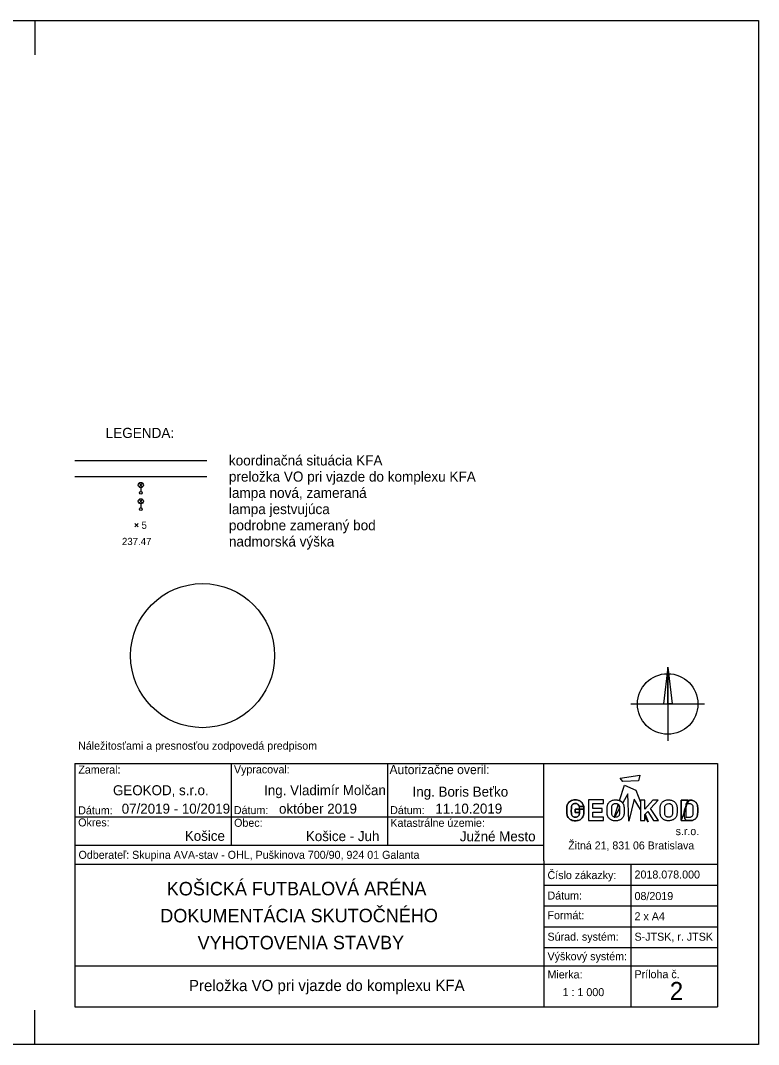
# Model space of a CAD drawing. Extents: x -263861 to -263441, y -1242367 to -1242070.
# Drawn here: x -263655.6 to -263441.4, y -1242367.2 to -1242070.2 of the extents above; entities that cross this region are included whole.
import ezdxf

# ---------------------------------------------------------------- set-up
doc = ezdxf.new("R2010")
doc.units = 0
for name, color, linetype in [('LEGENDA', 7, 'Continuous'), ('RAM_NA_TLAC_A3_1-1000', 7, 'Continuous'), ('ROZPISKA', 7, 'Continuous')]:
    doc.layers.add(name, color=color, linetype=linetype)

msp = doc.modelspace()

# ---------------------------------------------------------------- linework, layer by layer
at = {"layer": 'LEGENDA'}
for p, q in [((-263639.85, -1242197.79), (-263601.57, -1242197.79)), ((-263639.85, -1242202.49), (-263601.57, -1242202.49)), ((-263621.24, -1242205.47), (-263620.18, -1242204.41)), ((-263621.24, -1242204.41), (-263620.18, -1242205.47)), ((-263620.71, -1242205.69), (-263620.71, -1242206.79)), ((-263621.24, -1242210.18), (-263620.18, -1242209.12)), ((-263621.24, -1242209.12), (-263620.18, -1242210.18)), ((-263620.71, -1242210.4), (-263620.71, -1242211.5)), ((-263622.44, -1242217.06), (-263621.52, -1242216.14)), ((-263621.52, -1242217.06), (-263622.44, -1242216.14))]:
    msp.add_line(p, q, dxfattribs=at)
for centre, radius in [((-263620.71, -1242204.94), 0.75), ((-263620.71, -1242207.19), 0.4), ((-263620.71, -1242209.65), 0.75), ((-263620.71, -1242211.9), 0.4)]:
    msp.add_circle(centre, radius, dxfattribs=at)
at = {"layer": 'RAM_NA_TLAC_A3_1-1000'}
for p, q in [((-263651.44, -1242070.21), (-263651.44, -1242080.21)), ((-263441.44, -1242070.21), (-263441.44, -1242080.21)), ((-263651.44, -1242367.21), (-263651.44, -1242357.21))]:
    msp.add_line(p, q, dxfattribs=at)
msp.add_lwpolyline([(-263861.44, -1242070.21), (-263441.44, -1242070.21), (-263441.44, -1242367.21), (-263861.44, -1242367.21)], close=True, dxfattribs=at)
at = {"layer": 'ROZPISKA'}
for p, q in [((-263467.81, -1242257.78), (-263469.07, -1242268.44)), ((-263467.81, -1242257.78), (-263467.81, -1242279.1)), ((-263467.81, -1242257.78), (-263466.55, -1242268.44)), ((-263478.47, -1242268.44), (-263457.15, -1242268.44)), ((-263639.85, -1242285.66), (-263453.32, -1242285.66)), ((-263639.85, -1242285.66), (-263639.85, -1242356.25)), ((-263594.49, -1242285.66), (-263594.47, -1242309.37)), ((-263503.73, -1242313.89), (-263503.73, -1242285.66)), ((-263453.32, -1242285.66), (-263453.31, -1242356.25)), ((-263549.11, -1242285.67), (-263549.1, -1242309.36)), ((-263481.81, -1242296.44), (-263480.34, -1242292.01)), ((-263479.41, -1242294.53), (-263480.87, -1242297.14)), ((-263480.34, -1242292.01), (-263477.09, -1242293.39)), ((-263479.13, -1242302.43), (-263479.41, -1242294.53)), ((-263477.09, -1242293.39), (-263475.72, -1242296.88)), ((-263482.17, -1242297.54), (-263483.38, -1242301.22)), ((-263483, -1242296.23), (-263482.89, -1242296.22)), ((-263482.97, -1242297.29), (-263482.9, -1242297.29)), ((-263482.97, -1242297.29), (-263482.9, -1242297.29)), ((-263477.57, -1242296.03), (-263479.13, -1242302.43)), ((-263475.72, -1242299), (-263477.57, -1242296.03)), ((-263474.45, -1242296.3), (-263475.72, -1242296.3)), ((-263475.72, -1242296.88), (-263475.72, -1242299)), ((-263472.14, -1242296.3), (-263474.45, -1242298.91)), ((-263474.45, -1242298.91), (-263474.45, -1242296.3)), ((-263472.75, -1242298.71), (-263470.56, -1242296.3)), ((-263470.56, -1242296.3), (-263472.14, -1242296.3)), ((-263463.85, -1242296.32), (-263461.94, -1242296.32)), ((-263463.85, -1242302.28), (-263463.85, -1242296.32)), ((-263463.85, -1242296.32), (-263463.85, -1242302.28)), ((-263461.94, -1242296.32), (-263463.85, -1242296.32)), ((-263462.54, -1242297.36), (-263462.54, -1242301.24)), ((-263462.54, -1242297.36), (-263462.54, -1242301.24)), ((-263492.13, -1242298.15), (-263493.46, -1242298.15)), ((-263493.46, -1242298.15), (-263492.13, -1242298.15)), ((-263474.34, -1242300.38), (-263473.45, -1242302.66)), ((-263470.44, -1242302.28), (-263472.75, -1242298.71)), ((-263639.86, -1242301.15), (-263503.73, -1242301.15)), ((-263473.45, -1242302.66), (-263474.45, -1242301.05)), ((-263471.94, -1242302.28), (-263470.44, -1242302.28)), ((-263639.85, -1242309.36), (-263503.73, -1242309.35)), ((-263639.87, -1242314.91), (-263503.71, -1242314.9)), ((-263503.73, -1242313.89), (-263503.73, -1242332.05)), ((-263503.71, -1242314.9), (-263453.31, -1242314.9)), ((-263478.52, -1242314.91), (-263478.52, -1242333.06)), ((-263503.73, -1242320.95), (-263453.32, -1242320.96)), ((-263503.74, -1242327), (-263453.31, -1242327)), ((-263503.74, -1242333.05), (-263453.3, -1242333.06)), ((-263503.73, -1242332.05), (-263503.73, -1242356.24)), ((-263478.52, -1242333.06), (-263478.51, -1242356.24)), ((-263503.73, -1242339.11), (-263453.31, -1242339.1)), ((-263639.85, -1242344.35), (-263453.31, -1242344.34)), ((-263639.85, -1242356.25), (-263453.31, -1242356.25))]:
    msp.add_line(p, q, dxfattribs=at)
for points in [[(-263467.81, -1242257.78), (-263466.55, -1242268.44), (-263467.81, -1242268.44)], [(-263481.64, -1242289.95), (-263475.86, -1242289.12), (-263476.27, -1242290.77), (-263480.87, -1242290.92)], [(-263490.82, -1242296.28), (-263490.82, -1242302.28), (-263486.43, -1242302.28), (-263486.43, -1242301.22), (-263489.5, -1242301.22), (-263489.5, -1242299.78), (-263486.87, -1242299.78), (-263486.87, -1242298.74), (-263489.5, -1242298.74), (-263489.5, -1242297.34), (-263486.43, -1242297.34), (-263486.43, -1242296.28)]]:
    msp.add_lwpolyline(points, close=True, dxfattribs=at)
for points in [[(-263481.77, -1242298.75), (-263481.78, -1242298.62), (-263481.78, -1242298.46), (-263481.79, -1242298.31), (-263481.82, -1242298.16), (-263481.85, -1242298.03), (-263481.91, -1242297.88), (-263481.99, -1242297.74), (-263482.07, -1242297.63), (-263482.17, -1242297.54)], [(-263480.87, -1242297.14), (-263480.91, -1242297.08), (-263480.99, -1242297), (-263481.06, -1242296.92), (-263481.15, -1242296.85), (-263481.24, -1242296.78), (-263481.34, -1242296.7), (-263481.42, -1242296.65), (-263481.51, -1242296.59), (-263481.62, -1242296.53), (-263481.71, -1242296.48), (-263481.81, -1242296.44)], [(-263475.72, -1242296.3), (-263475.72, -1242302.28), (-263474.45, -1242302.28), (-263474.45, -1242300.49), (-263473.6, -1242299.6), (-263471.94, -1242302.28)], [(-263493.41, -1242299.92), (-263494.67, -1242299.92), (-263494.67, -1242298.93), (-263492.12, -1242298.93)], [(-263492.12, -1242298.93), (-263494.67, -1242298.93), (-263494.67, -1242299.92), (-263493.41, -1242299.92)], [(-263483.18, -1242301.27), (-263481.77, -1242298.75)], [(-263474.45, -1242301.05), (-263474.45, -1242300.49), (-263474.34, -1242300.38)], [(-263483.38, -1242301.22), (-263483.35, -1242301.23), (-263483.31, -1242301.24), (-263483.28, -1242301.25), (-263483.24, -1242301.26), (-263483.2, -1242301.27), (-263483.18, -1242301.27)]]:
    msp.add_lwpolyline(points, dxfattribs=at)
for centre, radius in [((-263602.79, -1242254.42), 20.9), ((-263467.81, -1242268.44), 8.78)]:
    msp.add_circle(centre, radius, dxfattribs=at)
for points in [[(-263492.12, -1242298.93), (-263492.12, -1242299.69), (-263492.13, -1242300.37), (-263492.27, -1242300.97), (-263492.56, -1242301.46), (-263493.01, -1242301.86), (-263493.48, -1242302.14), (-263494.1, -1242302.29), (-263494.66, -1242302.33), (-263495.24, -1242302.29), (-263495.83, -1242302.1), (-263496.33, -1242301.77), (-263496.72, -1242301.38), (-263496.97, -1242300.85), (-263497.09, -1242300.27), (-263497.11, -1242299.88), (-263497.11, -1242298.7), (-263497.07, -1242298.06), (-263496.89, -1242297.51), (-263496.6, -1242297.05), (-263496.02, -1242296.58), (-263495.4, -1242296.31), (-263494.68, -1242296.23), (-263493.92, -1242296.29), (-263493.13, -1242296.62), (-263492.5, -1242297.2), (-263492.13, -1242298.15), (-263492.12, -1242298.93), (-263492.13, -1242298.15)], [(-263492.13, -1242298.15), (-263492.5, -1242297.2), (-263493.13, -1242296.62), (-263493.92, -1242296.29), (-263494.68, -1242296.23), (-263495.4, -1242296.31), (-263496.02, -1242296.58), (-263496.6, -1242297.05), (-263496.89, -1242297.51), (-263497.07, -1242298.06), (-263497.11, -1242298.7), (-263497.11, -1242299.88), (-263497.09, -1242300.27), (-263496.97, -1242300.85), (-263496.72, -1242301.38), (-263496.33, -1242301.77), (-263495.83, -1242302.1), (-263495.24, -1242302.29), (-263494.66, -1242302.33), (-263494.1, -1242302.29), (-263493.48, -1242302.14), (-263493.01, -1242301.86), (-263492.56, -1242301.46), (-263492.27, -1242300.97), (-263492.13, -1242300.37), (-263492.12, -1242299.69), (-263492.12, -1242298.93), (-263492.13, -1242298.15), (-263492.12, -1242298.93)], [(-263493.45, -1242298.15), (-263493.58, -1242297.83), (-263493.87, -1242297.51), (-263494.27, -1242297.32), (-263494.66, -1242297.29), (-263495.06, -1242297.34), (-263495.38, -1242297.52), (-263495.62, -1242297.78), (-263495.73, -1242298.05), (-263495.74, -1242298.46), (-263495.77, -1242298.9), (-263495.78, -1242299.44), (-263495.77, -1242300.07), (-263495.72, -1242300.54), (-263495.55, -1242300.91), (-263495.3, -1242301.12), (-263494.99, -1242301.25), (-263494.67, -1242301.28), (-263494.29, -1242301.26), (-263493.9, -1242301.1), (-263493.61, -1242300.83), (-263493.45, -1242300.52), (-263493.41, -1242300.16), (-263493.41, -1242299.92), (-263493.45, -1242298.15), (-263493.41, -1242299.92)], [(-263493.41, -1242299.92), (-263493.41, -1242300.16), (-263493.45, -1242300.52), (-263493.61, -1242300.83), (-263493.9, -1242301.1), (-263494.29, -1242301.26), (-263494.67, -1242301.28), (-263494.99, -1242301.25), (-263495.3, -1242301.12), (-263495.55, -1242300.91), (-263495.72, -1242300.54), (-263495.77, -1242300.07), (-263495.78, -1242299.44), (-263495.77, -1242298.9), (-263495.74, -1242298.46), (-263495.73, -1242298.05), (-263495.62, -1242297.78), (-263495.38, -1242297.52), (-263495.06, -1242297.34), (-263494.66, -1242297.29), (-263494.27, -1242297.32), (-263493.87, -1242297.51), (-263493.58, -1242297.83), (-263493.45, -1242298.15), (-263493.41, -1242299.92), (-263493.45, -1242298.15)], [(-263482.89, -1242296.22), (-263482.86, -1242296.22), (-263482.68, -1242296.22), (-263482.35, -1242296.3), (-263481.89, -1242296.38), (-263481.47, -1242296.61), (-263481.08, -1242296.88), (-263480.76, -1242297.25), (-263480.58, -1242297.67), (-263480.47, -1242298.13), (-263480.47, -1242298.85), (-263480.45, -1242299.6), (-263480.46, -1242300.33), (-263480.53, -1242300.79), (-263480.7, -1242301.18), (-263480.92, -1242301.52), (-263481.23, -1242301.78), (-263481.55, -1242302.02), (-263481.95, -1242302.18), (-263482.39, -1242302.31), (-263482.87, -1242302.34), (-263483.31, -1242302.31), (-263483.71, -1242302.27), (-263484.05, -1242302.12), (-263484.38, -1242301.93), (-263484.69, -1242301.73), (-263484.97, -1242301.44), (-263485.19, -1242301.05), (-263485.35, -1242300.57), (-263485.41, -1242299.8), (-263485.35, -1242299.07), (-263485.38, -1242298.37), (-263485.32, -1242297.97), (-263485.23, -1242297.58), (-263485.04, -1242297.23), (-263484.79, -1242296.95), (-263484.52, -1242296.69), (-263484.18, -1242296.51), (-263483.79, -1242296.34), (-263483.38, -1242296.25), (-263483.11, -1242296.23), (-263483, -1242296.23)], [(-263482.9, -1242297.29), (-263482.85, -1242297.29), (-263482.71, -1242297.3), (-263482.47, -1242297.35), (-263482.21, -1242297.49), (-263481.97, -1242297.71), (-263481.82, -1242298.05), (-263481.76, -1242298.42), (-263481.77, -1242298.82), (-263481.76, -1242299.25), (-263481.78, -1242299.69), (-263481.76, -1242300.09), (-263481.82, -1242300.43), (-263481.89, -1242300.74), (-263482.09, -1242301.02), (-263482.37, -1242301.2), (-263482.68, -1242301.29), (-263482.93, -1242301.27), (-263483.15, -1242301.28), (-263483.4, -1242301.23), (-263483.63, -1242301.08), (-263483.86, -1242300.86), (-263484.02, -1242300.54), (-263484.07, -1242300.15), (-263484.05, -1242299.67), (-263484.06, -1242299.15), (-263484.05, -1242298.64), (-263484.04, -1242298.23), (-263483.97, -1242297.9), (-263483.79, -1242297.64), (-263483.54, -1242297.44), (-263483.26, -1242297.31), (-263483.06, -1242297.3), (-263482.97, -1242297.29)], [(-263482.9, -1242297.29), (-263482.85, -1242297.29), (-263482.71, -1242297.3), (-263482.47, -1242297.35), (-263482.21, -1242297.49), (-263481.97, -1242297.71), (-263481.82, -1242298.05), (-263481.76, -1242298.42), (-263481.77, -1242298.82), (-263481.76, -1242299.25), (-263481.78, -1242299.69), (-263481.76, -1242300.09), (-263481.82, -1242300.43), (-263481.89, -1242300.74), (-263482.09, -1242301.02), (-263482.37, -1242301.2), (-263482.68, -1242301.29), (-263482.93, -1242301.27), (-263483.15, -1242301.28), (-263483.4, -1242301.23), (-263483.63, -1242301.08), (-263483.86, -1242300.86), (-263484.02, -1242300.54), (-263484.07, -1242300.15), (-263484.05, -1242299.67), (-263484.06, -1242299.15), (-263484.05, -1242298.64), (-263484.04, -1242298.23), (-263483.97, -1242297.9), (-263483.79, -1242297.64), (-263483.54, -1242297.44), (-263483.26, -1242297.31), (-263483.06, -1242297.3), (-263482.97, -1242297.29)], [(-263467.51, -1242296.22), (-263467.95, -1242296.25), (-263468.42, -1242296.36), (-263468.81, -1242296.52), (-263469.13, -1242296.71), (-263469.41, -1242296.95), (-263469.64, -1242297.23), (-263469.84, -1242297.59), (-263469.94, -1242297.98), (-263469.99, -1242298.35), (-263469.99, -1242298.77), (-263470, -1242300.06), (-263469.95, -1242300.55), (-263469.78, -1242301.08), (-263469.55, -1242301.46), (-263469.32, -1242301.7), (-263468.98, -1242301.94), (-263468.67, -1242302.11), (-263468.34, -1242302.25), (-263467.94, -1242302.31), (-263467.51, -1242302.33), (-263467, -1242302.29), (-263466.55, -1242302.16), (-263466.19, -1242302.01), (-263465.83, -1242301.77), (-263465.56, -1242301.51), (-263465.34, -1242301.19), (-263465.17, -1242300.78), (-263465.1, -1242300.36), (-263465.08, -1242299.84), (-263465.09, -1242298.6), (-263465.11, -1242298.12), (-263465.21, -1242297.69), (-263465.41, -1242297.25), (-263465.69, -1242296.92), (-263466.12, -1242296.6), (-263466.51, -1242296.41), (-263466.97, -1242296.3), (-263467.42, -1242296.22), (-263467.51, -1242296.22), (-263467.51, -1242296.22), (-263467.51, -1242296.22)], [(-263467.52, -1242297.29), (-263467.85, -1242297.32), (-263468.16, -1242297.45), (-263468.41, -1242297.66), (-263468.56, -1242297.89), (-263468.64, -1242298.22), (-263468.67, -1242298.58), (-263468.68, -1242299.12), (-263468.68, -1242299.74), (-263468.68, -1242300.16), (-263468.61, -1242300.54), (-263468.45, -1242300.86), (-263468.24, -1242301.08), (-263468.01, -1242301.21), (-263467.75, -1242301.27), (-263467.55, -1242301.27), (-263467.34, -1242301.27), (-263467.02, -1242301.19), (-263466.7, -1242300.98), (-263466.54, -1242300.74), (-263466.44, -1242300.44), (-263466.39, -1242300.11), (-263466.39, -1242299.72), (-263466.39, -1242299.23), (-263466.39, -1242298.8), (-263466.4, -1242298.44), (-263466.47, -1242298.01), (-263466.61, -1242297.73), (-263466.84, -1242297.49), (-263467.12, -1242297.35), (-263467.35, -1242297.3), (-263467.52, -1242297.29), (-263467.52, -1242297.29), (-263467.52, -1242297.29)], [(-263461.94, -1242296.32), (-263461.32, -1242296.32), (-263460.93, -1242296.34), (-263460.65, -1242296.4), (-263460.28, -1242296.53), (-263459.92, -1242296.73), (-263459.57, -1242297.05), (-263459.31, -1242297.43), (-263459.18, -1242297.79), (-263459.1, -1242298.33), (-263459.09, -1242298.61), (-263459.09, -1242299.79), (-263459.11, -1242300.18), (-263459.13, -1242300.5), (-263459.19, -1242300.84), (-263459.36, -1242301.25), (-263459.66, -1242301.64), (-263460.1, -1242301.99), (-263460.45, -1242302.14), (-263460.82, -1242302.25), (-263461.13, -1242302.28), (-263461.23, -1242302.28), (-263463.85, -1242302.28), (-263461.94, -1242296.32), (-263463.85, -1242302.28)], [(-263463.85, -1242302.28), (-263461.23, -1242302.28), (-263461.13, -1242302.28), (-263460.82, -1242302.25), (-263460.45, -1242302.14), (-263460.1, -1242301.99), (-263459.66, -1242301.64), (-263459.36, -1242301.25), (-263459.19, -1242300.84), (-263459.13, -1242300.5), (-263459.11, -1242300.18), (-263459.09, -1242299.79), (-263459.09, -1242298.61), (-263459.1, -1242298.33), (-263459.18, -1242297.79), (-263459.31, -1242297.43), (-263459.57, -1242297.05), (-263459.92, -1242296.73), (-263460.28, -1242296.53), (-263460.65, -1242296.4), (-263460.93, -1242296.34), (-263461.32, -1242296.32), (-263461.94, -1242296.32), (-263463.85, -1242302.28), (-263461.94, -1242296.32)], [(-263462.54, -1242301.24), (-263462.16, -1242301.25), (-263461.77, -1242301.25), (-263461.35, -1242301.24), (-263461.28, -1242301.25), (-263461.12, -1242301.21), (-263460.88, -1242301.09), (-263460.58, -1242300.88), (-263460.43, -1242300.51), (-263460.39, -1242300.11), (-263460.4, -1242299.55), (-263460.39, -1242298.91), (-263460.4, -1242298.39), (-263460.43, -1242298.04), (-263460.56, -1242297.8), (-263460.83, -1242297.55), (-263461.13, -1242297.41), (-263461.53, -1242297.35), (-263461.81, -1242297.35), (-263462.37, -1242297.36), (-263462.54, -1242297.36)], [(-263462.54, -1242301.24), (-263462.16, -1242301.25), (-263461.77, -1242301.25), (-263461.35, -1242301.24), (-263461.28, -1242301.25), (-263461.12, -1242301.21), (-263460.88, -1242301.09), (-263460.58, -1242300.88), (-263460.43, -1242300.51), (-263460.39, -1242300.11), (-263460.4, -1242299.55), (-263460.39, -1242298.91), (-263460.4, -1242298.39), (-263460.43, -1242298.04), (-263460.56, -1242297.8), (-263460.83, -1242297.55), (-263461.13, -1242297.41), (-263461.53, -1242297.35), (-263461.81, -1242297.35), (-263462.37, -1242297.36), (-263462.54, -1242297.36)]]:
    msp.add_open_spline(points, degree=3, dxfattribs=at)

# ---------------------------------------------------------------- texts
at = {"layer": 'LEGENDA'}
for s, height, p in [('LEGENDA:', 2.939, (-263630.91, -1242191.29)), ('koordinačná situácia KFA', 2.9391, (-263595.15, -1242199.26)), ('preložka VO pri vjazde do komplexu KFA', 2.9391, (-263595.15, -1242203.96)), ('lampa nová, zameraná', 2.9391, (-263595.15, -1242208.66)), ('lampa jestvujúca', 2.9391, (-263595.15, -1242213.37)), ('5', 2.09, (-263620.51, -1242217.64)), ('podrobne zameraný bod', 2.9391, (-263595.15, -1242218.07)), ('237.47', 2.09, (-263626.19, -1242222.35)), ('nadmorská výška', 2.9391, (-263595.15, -1242222.77))]:
    msp.add_text(s, height=height, dxfattribs=at).set_placement(p)
at = {"layer": 'ROZPISKA'}
for s, height, rotation, p in [('Náležitosťami a presnosťou zodpovedá predpisom', 2.3187, 0.0016, (-263638.92, -1242281.69)), ('Zameral:', 2.319, 0.0016, (-263638.85, -1242288.63)), ('Vypracoval:', 2.3187, 0.0016, (-263593.69, -1242288.56)), ('Autorizačne overil:', 2.6427, 0.0016, (-263548.56, -1242288.79)), ('GEOKOD, s.r.o.', 2.8976, 0.0456, (-263628.79, -1242294.91)), ('Ing. Vladimír Molčan', 2.8982, 0.0456, (-263584.93, -1242294.9)), ('Ing. Boris Beťko', 2.8996, 0.0456, (-263541.85, -1242295.34)), ('07/2019 - 10/2019', 2.8976, 0.0456, (-263626.26, -1242300.26)), ('október 2019', 2.8976, 0.0456, (-263580.61, -1242300.26)), ('11.10.2019', 2.898, 0.0456, (-263535.23, -1242300.24)), ('Dátum:', 2.319, 0.0016, (-263638.88, -1242300.44)), ('Dátum:', 2.319, 0.0016, (-263593.71, -1242300.38)), ('Dátum:', 2.319, 0.0016, (-263548.36, -1242300.38)), ('Okres:', 2.319, 0.0016, (-263638.89, -1242303.95)), ('Obec:', 2.319, 0.0016, (-263593.64, -1242304.06)), ('Katastrálne územie:', 2.3187, 0.0016, (-263548.28, -1242304.07)), ('Košice', 2.899, 0.0456, (-263607.94, -1242308.14)), ('Košice - Juh', 2.8996, 0.0456, (-263572.8, -1242308.22)), ('Južné Mesto', 2.8996, 0.0456, (-263528.13, -1242308.28)), ('s.r.o.', 2.299, 0.0016, (-263465.5, -1242306.48)), ('Žitná 21, 831 06 Bratislava', 2.299, 0.0016, (-263496.68, -1242310.62)), ('Odberateľ: Skupina AVA-stav - OHL, Puškinova 700/90, 924 01 Galanta', 2.3181, 0.0016, (-263638.79, -1242313.35)), ('Číslo zákazky:', 2.3181, 0.0016, (-263502.69, -1242319.23)), ('KOŠICKÁ FUTBALOVÁ ARÉNA', 3.9145, 0.0456, (-263613.18, -1242323.97)), ('Dátum:', 2.319, 0.0016, (-263502.69, -1242325.16)), ('DOKUMENTÁCIA SKUTOČNÉHO', 3.9145, 0.0456, (-263615.06, -1242331.8)), ('Formát:', 2.319, 0.0016, (-263502.69, -1242330.86)), ('VYHOTOVENIA STAVBY', 3.9145, 0.0456, (-263604.23, -1242339.62)), ('Súrad. systém:', 2.3181, 0.0016, (-263502.69, -1242337.08)), ('Výškový systém:', 2.3181, 0.0016, (-263502.69, -1242342.78)), ('Mierka:', 2.319, 0.0016, (-263502.69, -1242348.04)), ('Príloha č.', 2.318, 0.0016, (-263477.43, -1242347.97)), ('Preložka VO pri vjazde do komplexu KFA', 3.2613, 0.0456, (-263606.74, -1242351.73))]:
    msp.add_text(s, height=height, rotation=rotation, dxfattribs=at).set_placement(p)
for s, height, p in [('2018.078.000', 2.322, (-263477.43, -1242319.06)), ('08/2019', 2.322, (-263477.43, -1242325.31)), ('2 x A4', 2.322, (-263477.43, -1242331.17)), ('S-JTSK, r. JTSK', 2.322, (-263477.43, -1242337.1)), ('1 : 1 000', 2.322, (-263498.31, -1242353.17)), ('2', 5.22, (-263467.2, -1242354.28))]:
    msp.add_text(s, height=height, dxfattribs=at).set_placement(p)

doc.saveas('drawing.dxf')
